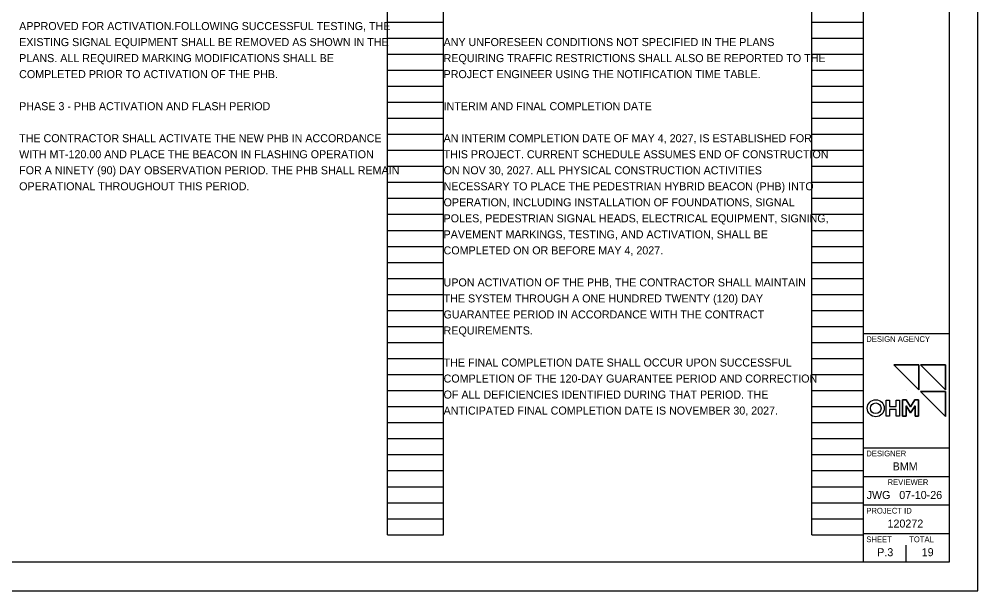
# Model space of a CAD drawing. Extents: x 0 to 34, y 0 to 22.
# Drawn here: x 17.24 to 34, y 0 to 9.99 of the extents above; entities that cross this region are included whole.
import ezdxf

# ---------------------------------------------------------------- set-up
doc = ezdxf.new("R2010")
doc.units = 0
for name, color, linetype in [('Default', 7, 'Continuous'), ('SH_Border', 7, 'Continuous'), ('SH_Cut_Line', 7, 'Continuous'), ('SH_Data', 7, 'Continuous'), ('SH_Text', 7, 'Continuous'), ('TX_P_Misc', 7, 'Continuous')]:
    doc.layers.add(name, color=color, linetype=linetype)

msp = doc.modelspace()

# ---------------------------------------------------------------- linework, layer by layer
at = {"layer": 'Default'}
for points in [[(32.966, 3.948), (32.966, 3.51), (32.53, 3.948)], [(33.433, 3.948), (33.433, 3.51), (32.997, 3.948)], [(33.433, 3.483), (33.433, 3.045), (32.997, 3.483)], [(32.397, 3.333), (32.457, 3.333), (32.457, 3.22), (32.571, 3.22), (32.571, 3.333), (32.631, 3.333), (32.631, 3.052), (32.571, 3.052), (32.571, 3.166), (32.457, 3.166), (32.457, 3.052), (32.397, 3.052)], [(32.9, 3.335), (32.963, 3.335), (32.963, 3.052), (32.903, 3.052), (32.903, 3.233), (32.824, 3.108), (32.745, 3.233), (32.745, 3.052), (32.685, 3.052), (32.685, 3.335), (32.748, 3.335), (32.824, 3.216)]]:
    msp.add_lwpolyline(points, close=True, dxfattribs=at)
at = {"layer": 'SH_Border'}
for p, q in [((32, 0.5), (32, 21.5)), ((32, 4.5), (33.5, 4.5)), ((32, 2.5), (33.5, 2.5)), ((32, 2), (33.5, 2)), ((32, 1.5), (33.5, 1.5)), ((32, 1), (33.5, 1))]:
    msp.add_line(p, q, dxfattribs=at)
msp.add_lwpolyline([(1.5, 21.5), (33.5, 21.5), (33.5, 0.5), (1.5, 0.5)], close=True, dxfattribs=at)
at = {"layer": 'SH_Cut_Line'}
msp.add_lwpolyline([(0, 0), (34, 0), (34, 22), (0, 22)], close=True, dxfattribs=at)
at = {"layer": 'SH_Data'}
for p, q in [((23.68, 0.98), (23.68, 21.14)), ((24.66, 0.98), (24.66, 21.14)), ((31.1, 0.98), (31.1, 21.14)), ((32, 0.98), (32, 21.14)), ((23.68, 9.94), (24.66, 9.94)), ((31.1, 9.94), (32, 9.94)), ((23.68, 9.66), (24.66, 9.66)), ((31.1, 9.66), (32, 9.66)), ((23.68, 9.38), (24.66, 9.38)), ((31.1, 9.38), (32, 9.38)), ((23.68, 9.1), (24.66, 9.1)), ((31.1, 9.1), (32, 9.1)), ((23.68, 8.82), (24.66, 8.82)), ((31.1, 8.82), (32, 8.82)), ((23.68, 8.54), (24.66, 8.54)), ((31.1, 8.54), (32, 8.54)), ((23.68, 8.26), (24.66, 8.26)), ((31.1, 8.26), (32, 8.26)), ((23.68, 7.98), (24.66, 7.98)), ((31.1, 7.98), (32, 7.98)), ((23.68, 7.7), (24.66, 7.7)), ((31.1, 7.7), (32, 7.7)), ((23.68, 7.42), (24.66, 7.42)), ((31.1, 7.42), (32, 7.42)), ((23.68, 7.14), (24.66, 7.14)), ((31.1, 7.14), (32, 7.14)), ((23.68, 6.86), (24.66, 6.86)), ((31.1, 6.86), (32, 6.86)), ((23.68, 6.58), (24.66, 6.58)), ((31.1, 6.58), (32, 6.58)), ((23.68, 6.3), (24.66, 6.3)), ((31.1, 6.3), (32, 6.3)), ((23.68, 6.02), (24.66, 6.02)), ((31.1, 6.02), (32, 6.02)), ((23.68, 5.74), (24.66, 5.74)), ((31.1, 5.74), (32, 5.74)), ((23.68, 5.46), (24.66, 5.46)), ((31.1, 5.46), (32, 5.46)), ((23.68, 5.18), (24.66, 5.18)), ((31.1, 5.18), (32, 5.18)), ((23.68, 4.9), (24.66, 4.9)), ((31.1, 4.9), (32, 4.9)), ((23.68, 4.62), (24.66, 4.62)), ((31.1, 4.62), (32, 4.62)), ((23.68, 4.34), (24.66, 4.34)), ((31.1, 4.34), (32, 4.34)), ((23.68, 4.06), (24.66, 4.06)), ((31.1, 4.06), (32, 4.06)), ((23.68, 3.78), (24.66, 3.78)), ((31.1, 3.78), (32, 3.78)), ((23.68, 3.5), (24.66, 3.5)), ((31.1, 3.5), (32, 3.5)), ((32.75, 3.5), (32.75, 3.5)), ((23.68, 3.22), (24.66, 3.22)), ((31.1, 3.22), (32, 3.22)), ((23.68, 2.94), (24.66, 2.94)), ((31.1, 2.94), (32, 2.94)), ((23.68, 2.66), (24.66, 2.66)), ((31.1, 2.66), (32, 2.66)), ((23.68, 2.38), (24.66, 2.38)), ((31.1, 2.38), (32, 2.38)), ((23.68, 2.1), (24.66, 2.1)), ((31.1, 2.1), (32, 2.1)), ((23.68, 1.82), (24.66, 1.82)), ((31.1, 1.82), (32, 1.82)), ((23.68, 1.54), (24.66, 1.54)), ((31.1, 1.54), (32, 1.54)), ((23.68, 1.26), (24.66, 1.26)), ((31.1, 1.26), (32, 1.26)), ((23.68, 0.98), (24.66, 0.98)), ((31.1, 0.98), (32, 0.98)), ((32.375, 0.675), (32.375, 0.675)), ((32.75, 0.5), (32.75, 0.8))]:
    msp.add_line(p, q, dxfattribs=at)
at = {"layer": 'TX_P_Misc'}
for p, q in [((32.745, 3.052), (32.745, 3.233)), ((32.745, 3.233), (32.824, 3.108)), ((32.824, 3.108), (32.903, 3.233)), ((32.903, 3.233), (32.903, 3.052))]:
    msp.add_line(p, q, dxfattribs=at)
for points in [[(32.53, 3.948), (32.966, 3.51), (32.966, 3.948), (32.53, 3.948)], [(32.997, 3.948), (33.433, 3.51), (33.433, 3.948), (32.997, 3.948)], [(32.997, 3.483), (33.433, 3.045), (33.433, 3.483), (32.997, 3.483)], [(32.824, 3.216), (32.748, 3.335), (32.685, 3.335), (32.685, 3.052), (32.745, 3.052)], [(32.903, 3.052), (32.963, 3.052), (32.963, 3.335), (32.9, 3.335), (32.824, 3.216)]]:
    msp.add_lwpolyline(points, dxfattribs=at)
msp.add_lwpolyline([(32.397, 3.333), (32.457, 3.333), (32.457, 3.22), (32.571, 3.22), (32.571, 3.333), (32.631, 3.333), (32.631, 3.052), (32.571, 3.052), (32.571, 3.166), (32.457, 3.166), (32.457, 3.052), (32.397, 3.052)], close=True, dxfattribs=at)
for radius in [0.148, 0.148, 0.0927, 0.0927]:
    msp.add_circle((32.215, 3.19), radius, dxfattribs=at)

# ---------------------------------------------------------------- texts
at = {"layer": 'SH_Data'}
for s, height, p in [('DESIGN AGENCY', 0.1, (32.05, 4.35)), ('DESIGNER', 0.1, (32.05, 2.35)), ('BMM', 0.14, (32.511, 2.105)), ('REVIEWER', 0.1, (32.422, 1.85)), ('JWG', 0.14, (32.056, 1.605)), ('07-10-26', 0.14, (32.627, 1.605)), ('PROJECT ID', 0.1, (32.05, 1.35)), ('120272', 0.14, (32.421, 1.105)), ('SHEET', 0.1, (32.05, 0.85)), ('TOTAL', 0.1, (32.8, 0.85)), ('P.3', 0.14, (32.241, 0.605)), ('19', 0.14, (33.019, 0.605))]:
    msp.add_text(s, height=height, dxfattribs=at).set_placement(p)
at = {"layer": 'SH_Text'}
for s, p in [('APPROVED FOR ACTIVATION.FOLLOWING SUCCESSFUL TESTING, THE ', (17.24, 9.8)), ('EXISTING SIGNAL EQUIPMENT SHALL BE REMOVED AS SHOWN IN THE ', (17.24, 9.52)), ('ANY UNFORESEEN CONDITIONS NOT SPECIFIED IN THE PLANS ', (24.66, 9.52)), ('PLANS. ALL REQUIRED MARKING MODIFICATIONS SHALL BE ', (17.24, 9.24)), ('REQUIRING TRAFFIC RESTRICTIONS SHALL ALSO BE REPORTED TO THE ', (24.66, 9.24)), ('COMPLETED PRIOR TO ACTIVATION OF THE PHB.', (17.24, 8.96)), ('PROJECT ENGINEER USING THE NOTIFICATION TIME TABLE.', (24.66, 8.96)), ('PHASE 3 - PHB ACTIVATION AND FLASH PERIOD', (17.24, 8.4)), ('INTERIM AND FINAL COMPLETION DATE', (24.66, 8.4)), ('THE CONTRACTOR SHALL ACTIVATE THE NEW PHB IN ACCORDANCE ', (17.24, 7.84)), ('AN INTERIM COMPLETION DATE OF MAY 4, 2027, IS ESTABLISHED FOR ', (24.66, 7.84)), ('WITH MT-120.00 AND PLACE THE BEACON IN FLASHING OPERATION ', (17.24, 7.56)), ('THIS PROJECT. CURRENT SCHEDULE ASSUMES END OF CONSTRUCTION ', (24.66, 7.56)), ('FOR A NINETY (90) DAY OBSERVATION PERIOD. THE PHB SHALL REMAIN ', (17.24, 7.28)), ('ON NOV 30, 2027. ALL PHYSICAL CONSTRUCTION ACTIVITIES ', (24.66, 7.28)), ('OPERATIONAL THROUGHOUT THIS PERIOD.', (17.24, 7)), ('NECESSARY TO PLACE THE PEDESTRIAN HYBRID BEACON (PHB) INTO ', (24.66, 7)), ('OPERATION, INCLUDING INSTALLATION OF FOUNDATIONS, SIGNAL ', (24.66, 6.72)), ('POLES, PEDESTRIAN SIGNAL HEADS, ELECTRICAL EQUIPMENT, SIGNING, ', (24.66, 6.44)), ('PAVEMENT MARKINGS, TESTING, AND ACTIVATION, SHALL BE ', (24.66, 6.16)), ('COMPLETED ON OR BEFORE MAY 4, 2027.', (24.66, 5.88)), ('UPON ACTIVATION OF THE PHB, THE CONTRACTOR SHALL MAINTAIN ', (24.66, 5.32)), ('THE SYSTEM THROUGH A ONE HUNDRED TWENTY (120) DAY ', (24.66, 5.04)), ('GUARANTEE PERIOD IN ACCORDANCE WITH THE CONTRACT ', (24.66, 4.76)), ('REQUIREMENTS.', (24.66, 4.48)), ('THE FINAL COMPLETION DATE SHALL OCCUR UPON SUCCESSFUL ', (24.66, 3.92)), ('COMPLETION OF THE 120-DAY GUARANTEE PERIOD AND CORRECTION ', (24.66, 3.64)), ('OF ALL DEFICIENCIES IDENTIFIED DURING THAT PERIOD. THE ', (24.66, 3.36)), ('ANTICIPATED FINAL COMPLETION DATE IS NOVEMBER 30, 2027.', (24.66, 3.08))]:
    msp.add_text(s, height=0.14, dxfattribs=at).set_placement(p)

doc.saveas('drawing.dxf')
